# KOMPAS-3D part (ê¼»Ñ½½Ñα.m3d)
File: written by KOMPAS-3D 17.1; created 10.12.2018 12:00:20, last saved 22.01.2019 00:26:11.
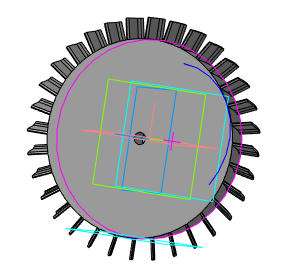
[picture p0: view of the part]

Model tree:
1. Эскиз:1
2. Операция вращения:1
     Угол 1 = 360
3. Смещенная плоскость:1
     Расстояние = 29
4. Эскиз:2
5. Спираль цилиндрическая:1
     Число витков = 0.325; Шаг = 86.1538; Высота = 28; Диаметр 1 = 74; Диаметр 2 = 10
6. Профиль крыльчатки
7. Кинематическая операция:1
8. Скругление:3
     Радиус = 0.4
9. Скругление:5
     Радиус = 0.4
10. Массив по концентрической сетке:2  (with: Операция вращения:1, Кинематическая операция:1, Смещенная плоскость:1, Спираль цилиндрическая:1)  (8 pattern instances)
     Шаг 2 = 360
11. Скругление:6
     Радиус = 0.4
12. Скругление:7
     Радиус = 0.4
13. Скругление:8
     Радиус = 0.4
14. Скругление:9
     Радиус = 0.4
15. Скругление:10
     Радиус = 0.4
16. Скругление:11
     Радиус = 0.4
17. Скругление:12
     Радиус = 0.4
18. Скругление:13
     Радиус = 0.4
19. Скругление:14
     Радиус = 0.4
20. Скругление:15
     Радиус = 0.4
21. Скругление:16
     Радиус = 0.4
22. Скругление:20
     Радиус = 0.4
23. Скругление:21
     Радиус = 0.4
24. Скругление:22
     Радиус = 0.4
25. Скругление:23
     Радиус = 0.4
26. Внутренняя полость
27. Вырезать элемент вращения:2
     Угол 1 = 360
28. Отверстие крепления
29. Вырезать элемент выдавливания:1
     Расстояние 1 = 10
30. Скругление:24
     Радиус = 2
31. Ограничительное поле
32. Вырезать элемент вращения:3
     Угол 1 = 360
33. Поддон
34. Операция выдавливания:1
     Расстояние 1 = 12
35. Обтекатель основания
36. Операция выдавливания:2
     Расстояние 1 = 5
37. Массив по концентрической сетке:3  (with: Операция выдавливания:2, Операция выдавливания:1)  (8 pattern instances)
     Шаг 2 = 360
38. Скругление:28
     Радиус = 4
39. Скругление:32
     Радиус = 4
40. Скругление:33
     Радиус = 4
41. Скругление:34
     Радиус = 4
42. Скругление:35
     Радиус = 4
43. Скругление:36
     Радиус = 4
44. Скругление:37
     Радиус = 4
45. Скругление:38
     Радиус = 4
46. Скругление:39
     Радиус = 0.1
47. Скругление:40
     Радиус = 0.1
48. Скругление:41
     Радиус = 0.1
49. Скругление:42
     Радиус = 0.1
50. Скругление:43
     Радиус = 0.1
51. Скругление:44
     Радиус = 0.1
52. Скругление:45
     Радиус = 0.1
53. Скругление:46
     Радиус = 0.1
54. Смещенная плоскость:3  (with: Профиль крыльчатки)
     Расстояние = 47
55. Операция выдавливания:4
     Расстояние 1 = 10; Расстояние 2 = 2
56. Массив по концентрической сетке:4  (with: Операция выдавливания:4, Смещенная плоскость:3, Операция выдавливания:1, Эскиз:8)  (32 pattern instances)
     Шаг 2 = 360
57. Эскиз:3
58. Элемент выдавливания:1  (with: Сечение модели:1)
     Расстояние 2 = 10

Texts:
  Точка начала. Х
  Точка начала. Y
  Точка начала. Z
